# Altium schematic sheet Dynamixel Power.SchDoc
size A4
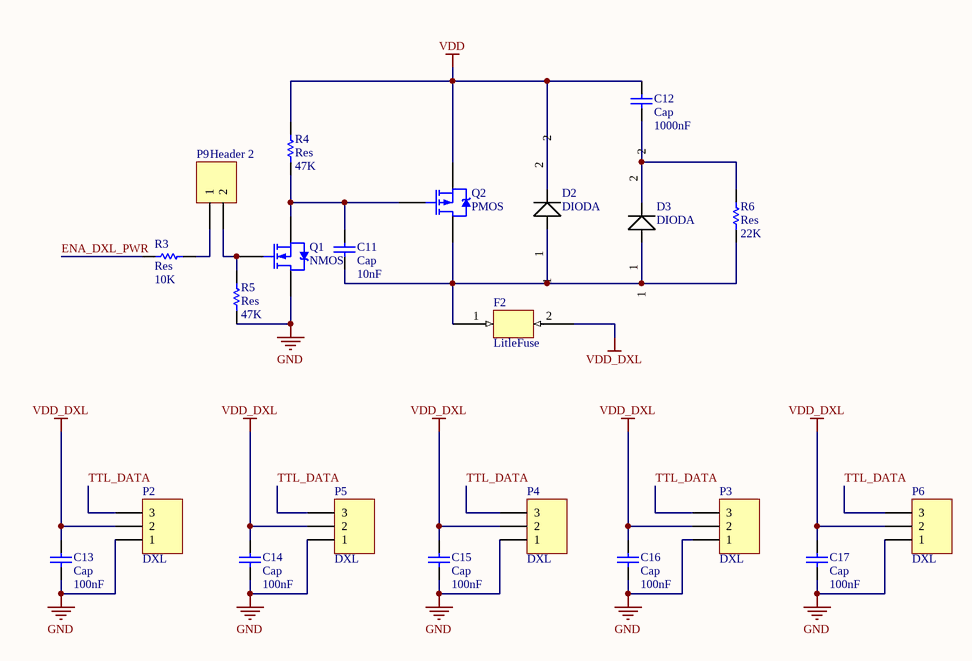
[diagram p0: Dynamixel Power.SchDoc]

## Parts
C11  Cap  value 10nF  [0603-CAP]
C12  Cap  value 1000nF  [0603-CAP]
C13  Cap  value 100nF  [0603-CAP]
C14  Cap  value 100nF  [0603-CAP]
C15  Cap  value 100nF  [0603-CAP]
C16  Cap  value 100nF  [0603-CAP]
C17  Cap  value 100nF  [0603-CAP]
D2  DIODA  [DIODE SS14 SODFL]
D3  DIODA  [DIODE SS14 SODFL]
F2  LitleFuse  [LitleFuse]
P2  DXL  [DXL]
P3  DXL  [DXL]
P4  DXL  [DXL]
P5  DXL  [DXL]
P6  DXL  [DXL]
P9  Header 2  [HDR1X2]
Q1  NMOS  [SOT23]
Q2  PMOS  [TO263]
R3  Res  value 10K  [0603-RES]
R4  Res  value 47K  [0603-RES]
R5  Res  value 47K  [0603-RES]
R6  Res  value 22K  [0603-RES]

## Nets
GND: C13.1 C14.1 C15.1 C16.1 C17.1 P2.1 P3.1 P4.1 P5.1 P6.1 Q1.3(D) R5.1
VDD: C12.2 D2.2 Q2.2(S) R4.2
VDD_DXL: C13.2 C14.2 C15.2 C16.2 C17.2 F2.2 P2.2 P3.2 P4.2 P5.2 P6.2
ENA_DXL_PWR: R3.1
TTL_DATA: P2.3 P3.3 P4.3 P5.3 P6.3
NetC11_1: C11.1 D2.1 D3.1 F2.1 Q2.3(D) R6.1
NetC11_2: C11.2 Q1.2(S) Q2.1(G) R4.1
NetC12_1: C12.1 D3.2 R6.2
NetP9_1: P9.1 R3.2
NetP9_2: P9.2 Q1.1(G) R5.2

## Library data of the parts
C11-C17 = Cap: Capacitor
P9 = Header 2: Header, 2-Pin
Q1 = NMOS: N-Channel Power MOSFET; Note: Pin 2 is electrically connected to pin 4.
Q2 = PMOS: P-Channel Power MOSFET; Note: Pin 4 not drawn and electrically connected to Pin 2.
R3-R6 = Res: Resistor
